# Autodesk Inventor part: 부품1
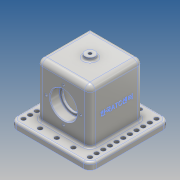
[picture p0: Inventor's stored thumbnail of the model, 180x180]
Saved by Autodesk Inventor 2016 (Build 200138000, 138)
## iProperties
Created: 2018-11
Part Number: 부품1
Material: 알루미늄 6061
Document SubType Name: Modeling
Designer: Administrator
Density: 2.7 g/cm^3
Appearance: 알루미늄 - 평지
Mass: 1019.88 g
Surface Area: 779.651 cm^2
Volume: 377.732 cm^3
Author: Administrator
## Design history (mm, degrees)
sketch "스케치1"
  geometry: L1 (60, -60)-(-60, -60); L2 (-60, -60)-(-60, 60); L3 (-60, 60)-(60, 60); L4 (60, 60)-(60, -60); L5 (60, -60)-(-60, 60); L6 (-60, -60)-(60, 60); 1 further point
  constraints: 12 end point, 2 midpoint, 2 parallel, 1 horizontal, 1 perpendicular
  dimensions: "d0" = 120 distance of L2.end L3.end; "d1" = 120 distance of L1.end L2.end
extrude "돌출1" new body sketch "스케치1" distance "d2" = 10; taper "d3" = 0 deg
sketch "스케치2"
  geometry: L1 (40, -40)-(-40, -40); L2 (-40, -40)-(-40, 40); L3 (-40, 40)-(40, 40); L4 (40, 40)-(40, -40); L5 (40, -40)-(-40, 40); L6 (-40, -40)-(40, 40); 1 further point
  constraints: 12 end point, 2 midpoint, 2 parallel, 1 horizontal, 1 perpendicular
  dimensions: "d4" = 80 distance of L2.end L3.end; "d5" = 80 distance of L1.end L2.end
extrude "돌출2" join sketch "스케치2" distance "d6" = 80; taper "d7" = 0 deg
sketch "스케치3"
  geometry: L1 (-40, 10)-(-40, 90) reference; L2 (-40, 48)-(40, 48); L3 (40, 10)-(40, 90) reference; L4 (-60, 0)-(60, 0) reference; L5 (-40, 68)-(-26.6, 68); L6 (-26, 67.4)-(-26, 64.5); L7 (-26, 64.5)-(26, 64.5); L8 (26, 64.5)-(26, 67.4); L9 (26.6, 68)-(40, 68); A1 r 0.6 centre (-26.6, 67.4) between (-26, 67.4) and (-26.6, 68); A2 r 0.6 centre (26.6, 67.4) between (26.6, 68) and (26, 67.4); 3 further points
  constraints: 12 end point, 8 point on line, 4 point on circle, 4 tangent, 3 perpendicular, 2 centre point, 2 equal length, 2 horizontal, 1 equal radius, 1 vertical
  dimensions: "d8" = 48 distance between parallel lines of L4 L2; "d9" = 33 diameter of L7 L2; "d10" = 40 diameter of L5 L2; "d11" = 14 distance from line of L5.start L6; "d44" = 0.6 radius of A1
revolve "회전1" sketch "스케치3" stored, may be unused: angle "d12" = 90 deg
sketch "스케치4"
  geometry: L1 (30, 23)-(-30, 23); L2 (-30, 23)-(-30, -23); L3 (-30, -23)-(30, -23); L4 (30, -23)-(30, 23); L5 (30, 23)-(-30, -23); L6 (-30, 23)-(30, -23); 1 further point
  constraints: 12 end point, 2 midpoint, 2 parallel, 1 horizontal, 1 perpendicular
  dimensions: "d13" = 60 distance of L3.end L2.end; "d14" = 46 distance of L2.end L1.end
extrude "돌출3" cut sketch "스케치4" distance "d15" = 80; taper "d16" = 0 deg
fillet "모깎기1" dims "d17" = 8
fillet "모깎기2" dims "d18" = 10
sketch "스케치5"
  geometry: C1 r 7.5 at (0, 0); 1 further point
  constraints: 1 centre point, 1 coincident
  dimensions: "d20" = 15 diameter of C1
extrude "돌출4" join sketch "스케치5" distance "d21" = 5; taper "d22" = 0 deg
hole "구멍1" diameter "d25" = 4.917; stored, may be unused: countersink angle "d29" = 90 deg, drill point angle "d31" = 118 deg; dims "d23" = 10, "d24" = 10, "d26" = 12, "d27" = 4, "d28" = 2, "d30" = 17.1
fillet "모깎기4" dims "d40" = 3
chamfer "모따기1" distance "d41" = 1; stored, may be unused: second distance "d42" = 2, angle "d43" = 45 deg
sketch "스케치7"
  geometry: C1 r 19.4 at (32, -34) reference; A1 r 26 centre (32, -34) between (32, -8) and (6, -34); 3 further points
  constraints: 4 point on circle, 2 horizontal alignment, 2 vertical alignment, 1 centre point, 1 coincident
  dimensions: "d45" = 52 diameter of A1
hole "구멍3" sketch "스케치7" at (32, -8), (6, -34), (32, -60), (58, -34) diameter "d46" = 3.242; stored, may be unused: countersink angle "d50" = 90 deg, drill point angle "d52" = 118 deg; dims "d47" = 8, "d48" = 4, "d49" = 2, "d51" = 10
sketch "스케치8"
  geometry: C1 r 3.3 at (-50, -50); C2 r 3.3 at (-50, 50); C3 r 3.3 at (50, 50); C4 r 3.3 at (50, -50); C5 r 3.3 at (0, -50); C6 r 3.3 at (0, 50); C7 r 3.3 at (-25, -50); C8 r 3.3 at (25, -50); C9 r 3.3 at (-25, 50); C10 r 3.3 at (25, 50); C11 r 3.3 at (-50, -40); C12 r 3.3 at (-50, -30); C13 r 3.3 at (-50, -20); C14 r 3.3 at (-50, -10); C15 r 3.3 at (-50, 0); C16 r 3.3 at (-50, 10); C17 r 3.3 at (-50, 20); C18 r 3.3 at (-50, 30); C19 r 3.3 at (-50, 40); C20 r 3.3 at (50, -40); C21 r 3.3 at (50, -30); C22 r 3.3 at (50, -20); C23 r 3.3 at (50, -10); C24 r 3.3 at (50, 0); C25 r 3.3 at (50, 10); C26 r 3.3 at (50, 20); C27 r 3.3 at (50, 30); C28 r 3.3 at (50, 40); A1 r 10 centre (-50, -50) between (-60, -50) and (-50, -60) reference; A2 r 10 centre (-50, 50) between (-50, 60) and (-60, 50) reference; A3 r 10 centre (50, 50) between (60, 50) and (50, 60) reference; A4 r 10 centre (50, -50) between (50, -60) and (60, -50) reference; 1 further point
  constraints: 28 centre point, 28 vertical alignment, 9 equal radius, 4 coincident, 4 horizontal alignment
  dimensions: "d53" = 6.6 diameter of C1; "d54" = 6.6 diameter of C2; "d55" = 6.6 diameter of C3; "d56" = 6.6 diameter of C4; "d57" = 6.6 diameter of C5; "d58" = 6.6 diameter of C6; "d59" = 6.6 diameter of C7; "d60" = 6.6 diameter of C8; "d61" = 6.6 diameter of C9; "d62" = 6.6 diameter of C10; "d63" = 10 distance of C11.centre C1.centre; "d64" = 10 distance of C12.centre C11.centre; "d65" = 10 distance of C2.centre C19.centre; "d66" = 10 distance of C19.centre C18.centre; "d67" = 10 distance of C18.centre C17.centre; "d68" = 10 distance of C17.centre C16.centre; "d69" = 10 distance of C16.centre C15.centre; "d70" = 10 distance of C15.centre C14.centre; "d71" = 10 distance of C13.centre C12.centre; "d72" = 25 distance of C1.centre C7.centre; "d73" = 25 distance of C10.centre C3.centre; "d74" = 25 distance of A2.centre C9.centre; "d75" = 25 distance of C8.centre C4.centre; "d78" = 6.6 diameter of C20; "d79" = 6.6 diameter of C21; "d80" = 6.6 diameter of C22; "d81" = 6.6 diameter of C23; "d82" = 6.6 diameter of C24; "d83" = 6.6 diameter of C25; "d84" = 6.6 diameter of C26; "d85" = 6.6 diameter of C27; "d86" = 6.6 diameter of C28; "d87" = 10 distance of C20.centre C4.centre; "d88" = 10 distance of C21.centre C20.centre; "d89" = 10 distance of C22.centre C21.centre; "d90" = 10 distance of C23.centre C22.centre; "d91" = 10 distance of C24.centre C23.centre; "d92" = 10 distance of C25.centre C24.centre; "d93" = 10 distance of C26.centre C25.centre; "d94" = 10 distance of C27.centre C26.centre; "d95" = 10 distance of C28.centre C27.centre
extrude "돌출5" cut sketch "스케치8" stored distance "d76" = 5; taper "d77" = 0 deg
extrude "돌출6" cut sketch "스케치8" stored distance "d96" = 5; taper "d97" = 0 deg
sketch "스케치9"
  geometry: 2 further points
  constraints: 1 horizontal alignment, 1 other
  dimensions: "d98" = 48 distance of point (82, 32) point (34, 32)
feature "엠보싱1" sketch "스케치9" dims "d99" = 0.5, "d100" = 0
node "솔리드1"
mirror "대칭2"
